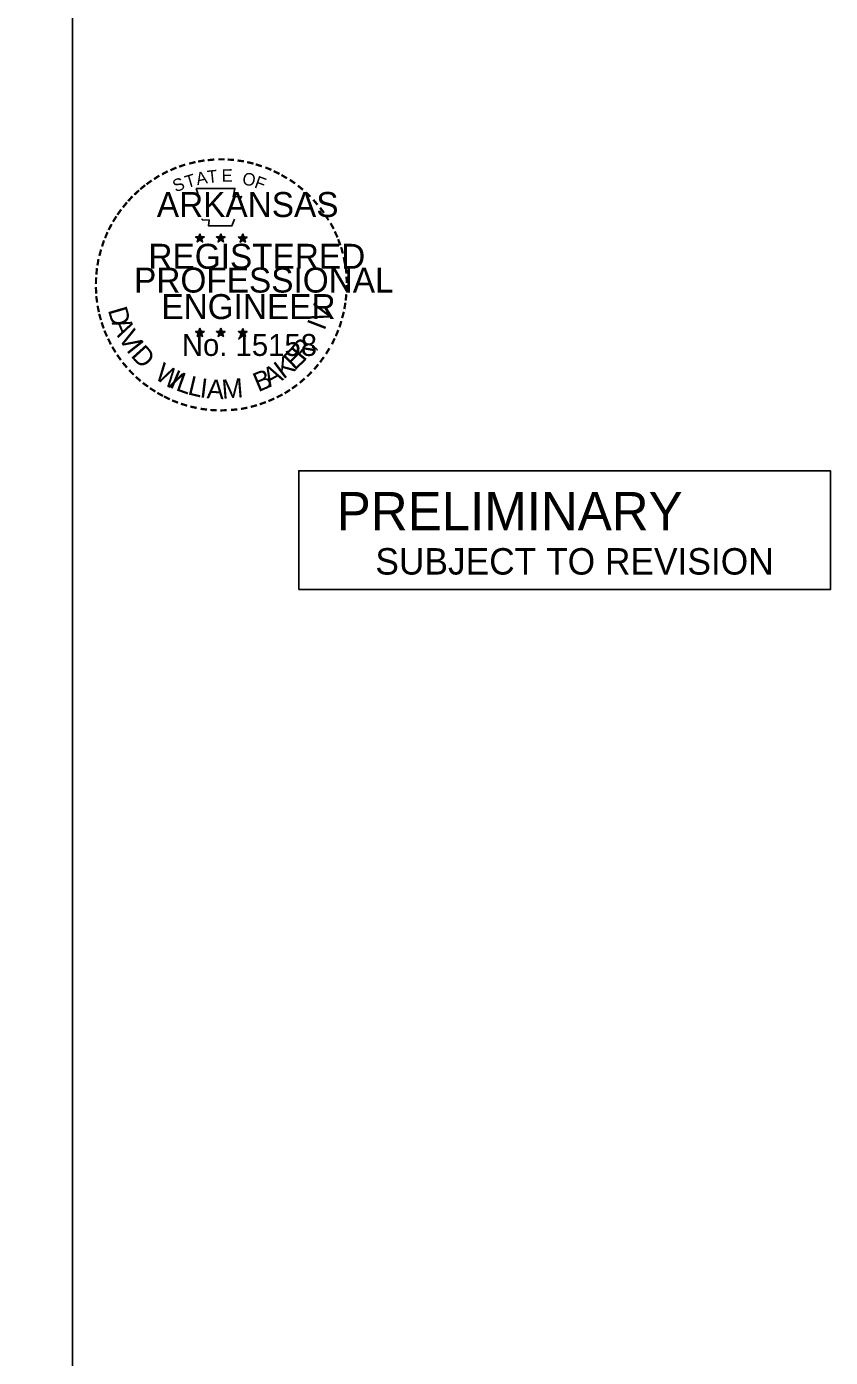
# Model space of a CAD drawing. Extents: x 1371343 to 1376243, y 378740 to 382184.
# Drawn here: x 1373024 to 1373353, y 380374 to 380917 of the extents above; entities that cross this region are included whole.
import ezdxf

# ---------------------------------------------------------------- set-up
doc = ezdxf.new("R2010")
doc.units = 0
for name, color, linetype in [('Default', 7, 'Continuous'), ('R_Border PE', 7, 'Continuous'), ('SHET_Border-Lines', 7, 'Continuous'), ('SHET_Stamp-PE-Chief-Eng', 7, 'Continuous')]:
    doc.layers.add(name, color=color, linetype=linetype)

msp = doc.modelspace()

# ---------------------------------------------------------------- linework, layer by layer
at = {"layer": 'Default'}
for points in [[(1371342.92, 380940.49), (1371342.92, 379840.49), (1373042.92, 379840.49), (1373042.92, 380940.49)], [(1373135.48, 380687.25), (1373352.88, 380687.25), (1373352.88, 380735.79), (1373135.48, 380735.79)]]:
    msp.add_lwpolyline(points, close=True, dxfattribs=at)
at = {"layer": 'R_Border PE'}
for p, q in [((1373095.08, 380832.67), (1373094.87, 380831.39)), ((1373095.08, 380830.81), (1373095.08, 380832.67)), ((1373095.08, 380832.67), (1373095.33, 380831.4)), ((1373103.6, 380832.67), (1373103.39, 380831.39)), ((1373103.6, 380830.81), (1373103.6, 380832.67)), ((1373103.6, 380832.67), (1373103.85, 380831.4)), ((1373112.59, 380832.61), (1373112.38, 380831.33)), ((1373112.59, 380830.75), (1373112.59, 380832.61)), ((1373112.59, 380832.61), (1373112.84, 380831.34)), ((1373093.3, 380831.38), (1373095.08, 380830.81)), ((1373093.3, 380831.38), (1373094.59, 380831.15)), ((1373093.3, 380831.38), (1373094.51, 380830.75)), ((1373093.98, 380829.3), (1373095.08, 380830.81)), ((1373093.98, 380829.3), (1373094.62, 380830.54)), ((1373093.98, 380829.3), (1373095.07, 380830.4)), ((1373096.17, 380829.3), (1373095.07, 380830.39)), ((1373096.85, 380831.38), (1373095.08, 380830.81)), ((1373096.17, 380829.3), (1373095.08, 380830.81)), ((1373096.85, 380831.38), (1373095.39, 380831.13)), ((1373096.17, 380829.3), (1373095.47, 380830.78)), ((1373096.85, 380831.38), (1373095.81, 380830.86)), ((1373101.82, 380831.38), (1373103.6, 380830.81)), ((1373101.82, 380831.38), (1373103.11, 380831.15)), ((1373101.82, 380831.38), (1373103.03, 380830.75)), ((1373102.5, 380829.3), (1373103.6, 380830.81)), ((1373102.5, 380829.3), (1373103.14, 380830.54)), ((1373102.5, 380829.3), (1373103.59, 380830.4)), ((1373104.68, 380829.3), (1373103.59, 380830.39)), ((1373105.37, 380831.38), (1373103.6, 380830.81)), ((1373104.68, 380829.3), (1373103.6, 380830.81)), ((1373105.37, 380831.38), (1373103.91, 380831.13)), ((1373104.68, 380829.3), (1373103.98, 380830.78)), ((1373105.37, 380831.38), (1373104.33, 380830.86)), ((1373110.81, 380831.32), (1373112.59, 380830.75)), ((1373110.81, 380831.32), (1373112.1, 380831.09)), ((1373110.81, 380831.32), (1373112.02, 380830.69)), ((1373111.49, 380829.23), (1373112.59, 380830.75)), ((1373111.49, 380829.23), (1373112.13, 380830.48)), ((1373111.49, 380829.23), (1373112.58, 380830.34)), ((1373113.68, 380829.23), (1373112.58, 380830.33)), ((1373114.36, 380831.32), (1373112.59, 380830.75)), ((1373113.68, 380829.23), (1373112.59, 380830.75)), ((1373114.36, 380831.32), (1373112.9, 380831.07)), ((1373113.68, 380829.23), (1373112.98, 380830.72)), ((1373114.36, 380831.32), (1373113.32, 380830.8)), ((1373095.06, 380794.05), (1373094.85, 380792.77)), ((1373095.06, 380792.19), (1373095.06, 380794.05)), ((1373095.06, 380794.05), (1373095.31, 380792.78)), ((1373103.57, 380794.05), (1373103.36, 380792.77)), ((1373103.57, 380792.19), (1373103.57, 380794.05)), ((1373103.57, 380794.05), (1373103.82, 380792.78)), ((1373112.58, 380794), (1373112.37, 380792.71)), ((1373112.58, 380792.14), (1373112.58, 380794)), ((1373112.58, 380794), (1373112.83, 380792.72)), ((1373093.28, 380792.76), (1373095.06, 380792.19)), ((1373093.28, 380792.76), (1373094.57, 380792.53)), ((1373093.28, 380792.76), (1373094.49, 380792.13)), ((1373093.96, 380790.67), (1373095.06, 380792.19)), ((1373093.96, 380790.67), (1373094.6, 380791.92)), ((1373093.96, 380790.67), (1373095.05, 380791.78)), ((1373096.15, 380790.67), (1373095.05, 380791.77)), ((1373096.83, 380792.76), (1373095.06, 380792.19)), ((1373096.15, 380790.67), (1373095.06, 380792.19)), ((1373096.83, 380792.76), (1373095.37, 380792.51)), ((1373096.15, 380790.67), (1373095.45, 380792.16)), ((1373096.83, 380792.76), (1373095.79, 380792.23)), ((1373101.79, 380792.76), (1373103.57, 380792.19)), ((1373101.79, 380792.76), (1373103.08, 380792.53)), ((1373101.79, 380792.76), (1373103, 380792.13)), ((1373102.47, 380790.67), (1373103.57, 380792.19)), ((1373102.47, 380790.67), (1373103.11, 380791.92)), ((1373102.47, 380790.67), (1373103.56, 380791.78)), ((1373104.66, 380790.67), (1373103.56, 380791.77)), ((1373105.34, 380792.76), (1373103.57, 380792.19)), ((1373104.66, 380790.67), (1373103.57, 380792.19)), ((1373105.34, 380792.76), (1373103.88, 380792.51)), ((1373104.66, 380790.67), (1373103.96, 380792.16)), ((1373105.34, 380792.76), (1373104.3, 380792.23)), ((1373110.8, 380792.7), (1373112.58, 380792.14)), ((1373110.8, 380792.7), (1373112.09, 380792.47)), ((1373110.8, 380792.7), (1373112.01, 380792.08)), ((1373111.48, 380790.62), (1373112.58, 380792.14)), ((1373111.48, 380790.62), (1373112.12, 380791.87)), ((1373111.48, 380790.62), (1373112.57, 380791.73)), ((1373113.67, 380790.62), (1373112.57, 380791.71)), ((1373114.35, 380792.7), (1373112.58, 380792.14)), ((1373113.67, 380790.62), (1373112.58, 380792.14)), ((1373114.35, 380792.7), (1373112.89, 380792.45)), ((1373113.67, 380790.62), (1373112.97, 380792.11)), ((1373114.35, 380792.7), (1373113.31, 380792.18))]:
    msp.add_line(p, q, dxfattribs=at)
for points in [[(1373093.51, 380851.15), (1373094.88, 380846.94)], [(1373111.42, 380846.45), (1373112.14, 380847.9), (1373108.65, 380847.78), (1373109.4, 380851.15), (1373093.51, 380851.15)], [(1373096.02, 380838.8), (1373096.02, 380838.35), (1373098.89, 380838.26), (1373098.61, 380835.84), (1373108.15, 380835.84), (1373109.18, 380838.58)], [(1373103.6, 380832.67), (1373104.68, 380829.3), (1373101.82, 380831.38), (1373105.37, 380831.38), (1373102.5, 380829.3), (1373103.6, 380832.67)], [(1373112.59, 380832.61), (1373113.68, 380829.23), (1373110.81, 380831.32), (1373114.36, 380831.32), (1373111.49, 380829.23), (1373112.59, 380832.61)], [(1373095.06, 380794.05), (1373096.15, 380790.67), (1373093.28, 380792.76), (1373096.83, 380792.76), (1373093.96, 380790.67), (1373095.06, 380794.05)], [(1373103.57, 380794.05), (1373104.66, 380790.67), (1373101.79, 380792.76), (1373105.34, 380792.76), (1373102.47, 380790.67), (1373103.57, 380794.05)], [(1373112.58, 380794), (1373113.67, 380790.62), (1373110.8, 380792.7), (1373114.35, 380792.7), (1373111.48, 380790.62), (1373112.58, 380794)]]:
    msp.add_lwpolyline(points, dxfattribs=at)
for centre, radius in [((1373095.08, 380830.81), 0.878), ((1373103.59, 380830.81), 0.878), ((1373095.08, 380830.81), 0.737), ((1373095.08, 380830.81), 0.59), ((1373095.08, 380830.81), 0.505), ((1373095.08, 380830.81), 0.381), ((1373095.08, 380830.81), 0.253), ((1373095.08, 380830.81), 0.151), ((1373103.59, 380830.81), 0.737), ((1373103.59, 380830.81), 0.59), ((1373103.59, 380830.81), 0.505), ((1373103.59, 380830.81), 0.381), ((1373103.59, 380830.81), 0.253), ((1373103.59, 380830.81), 0.151), ((1373112.59, 380830.74), 0.878), ((1373112.59, 380830.74), 0.737), ((1373112.59, 380830.74), 0.59), ((1373112.59, 380830.74), 0.505), ((1373112.59, 380830.74), 0.381), ((1373112.59, 380830.74), 0.253), ((1373112.59, 380830.74), 0.151), ((1373095.05, 380792.18), 0.878), ((1373095.05, 380792.18), 0.737), ((1373095.05, 380792.18), 0.59), ((1373095.05, 380792.18), 0.505), ((1373095.05, 380792.18), 0.381), ((1373095.05, 380792.18), 0.253), ((1373095.05, 380792.18), 0.151), ((1373103.57, 380792.18), 0.878), ((1373103.57, 380792.18), 0.737), ((1373103.57, 380792.18), 0.59), ((1373103.57, 380792.18), 0.505), ((1373103.57, 380792.18), 0.381), ((1373103.57, 380792.18), 0.253), ((1373103.57, 380792.18), 0.151), ((1373112.58, 380792.13), 0.878), ((1373112.58, 380792.13), 0.737), ((1373112.58, 380792.13), 0.59), ((1373112.58, 380792.13), 0.505), ((1373112.58, 380792.13), 0.381), ((1373112.58, 380792.13), 0.253), ((1373112.58, 380792.13), 0.151)]:
    msp.add_circle(centre, radius, dxfattribs=at)
at = {"layer": 'SHET_Border-Lines'}
msp.add_lwpolyline([(1371342.92, 379840.49), (1373042.92, 379840.49), (1373042.92, 380940.49), (1371342.92, 380940.49)], close=True, dxfattribs=at)
at = {"layer": 'SHET_Stamp-PE-Chief-Eng'}
msp.add_lwpolyline([(1373095.08, 380832.67), (1373096.17, 380829.3), (1373093.3, 380831.38), (1373096.85, 380831.38), (1373093.98, 380829.3), (1373095.08, 380832.67)], dxfattribs=at)

# ---------------------------------------------------------------- texts
at = {"layer": 'Default'}
for s, height, p in [('PRELIMINARY', 15.6, (1373151.04, 380711.52)), ('SUBJECT TO REVISION', 10.8, (1373166.81, 380693.39))]:
    msp.add_text(s, height=height, dxfattribs=at).set_placement(p)
at = {"layer": 'R_Border PE'}
for s, height, rotation, p in [('-', 8.16, 24.3072, (1373083.89, 380855.53)), ('-', 8.16, 19.1761, (1373087.12, 380856.9)), ('-', 8.16, 13.6302, (1373090.95, 380858.13)), ('-', 8.16, 10.2193, (1373094.41, 380858.96)), ('T', 5.1, 6.0228, (1373098.32, 380853.33)), ('-', 8.16, 5.8968, (1373098.12, 380859.52)), ('-', 8.16, 0.1862, (1373102.06, 380859.89)), ('E', 5.1, 0.8323, (1373103.96, 380853.89)), ('-', 8.16, 357.743, (1373105.75, 380859.82)), ('-', 8.16, 352.1617, (1373109.54, 380859.53)), ('-', 8.16, 347.2049, (1373113.21, 380858.95)), ('-', 8.16, 342.3362, (1373116.45, 380858.16)), ('-', 8.16, 337.8551, (1373120.2, 380857.02)), ('-', 8.16, 36.2317, (1373074.67, 380850.01)), ('-', 8.16, 34.0636, (1373077.62, 380852.03)), ('-', 8.16, 28.7918, (1373080.66, 380853.91)), ('S', 5.1, 21.594, (1373085.12, 380849.51)), ('T', 5.1, 16.4036, (1373089.78, 380851.2)), ('A', 5.1, 11.2132, (1373093.99, 380852.48)), ('O', 5.1, 350.4515, (1373112.14, 380852.82)), ('F', 5.1, 340.0707, (1373117, 380851.65)), ('-', 8.16, 334.1211, (1373123.41, 380855.64)), ('-', 8.16, 329.6409, (1373126.37, 380854.2)), ('-', 8.16, 325.8627, (1373129.65, 380852.36)), ('-', 8.16, 48.4231, (1373067.75, 380843.52)), ('-', 8.16, 42.9622, (1373070.03, 380845.96)), ('-', 8.16, 38.9507, (1373072.24, 380848.08)), ('-', 8.16, 320.5297, (1373132.76, 380850.19)), ('-', 8.16, 315.5786, (1373135.81, 380847.7)), ('-', 8.16, 54.2325, (1373063.59, 380838.15)), ('-', 8.16, 50.6142, (1373065.69, 380841.04)), ('-', 8.16, 309.8797, (1373138.71, 380844.89)), ('-', 8.16, 306.6522, (1373141.39, 380841.82)), ('-', 8.16, 58.0706, (1373061.93, 380835.46)), ('-', 7.14, 303.6753, (1373143.87, 380838.92)), ('-', 8.16, 299.6684, (1373145.5, 380835.83)), ('-', 8.16, 67.7743, (1373059.01, 380829.21)), ('-', 8.16, 62.8713, (1373060.33, 380832.33)), ('-', 8.16, 294.6628, (1373147.15, 380832.71)), ('-', 8.16, 75.461, (1373056.89, 380822.36)), ('-', 8.16, 72.3945, (1373057.9, 380826)), ('-', 8.16, 290.5728, (1373148.46, 380829.77)), ('-', 8.16, 285.1233, (1373149.65, 380826.81)), ('-', 8.16, 81.2013, (1373056.22, 380818.72)), ('-', 8.16, 280.5493, (1373150.67, 380823.02)), ('-', 8.16, 85.1863, (1373055.83, 380815.2)), ('-', 8.16, 276.5962, (1373151.5, 380819.11)), ('-', 8.16, 94.1959, (1373055.88, 380807.93)), ('-', 8.16, 89.0622, (1373055.7, 380811.62)), ('-', 8.16, 274.3301, (1373151.81, 380815.42)), ('-', 8.16, 269.9407, (1373151.98, 380812.2)), ('-', 8.16, 98.9479, (1373056.25, 380804.53)), ('V', 7.85, 72.6573, (1373147.11, 380795.57)), ('-', 8.16, 260.9953, (1373151.52, 380805.47)), ('-', 8.16, 263.5172, (1373151.88, 380808.8)), ('-', 8.16, 101.7149, (1373056.94, 380800.79)), ('-', 8.16, 105.4578, (1373057.76, 380797.75)), ('D', 7.85, 286.2848, (1373057.39, 380801.49)), ('-', 8.16, 255.7626, (1373150.96, 380802.01)), ('-', 8.16, 109.0874, (1373058.86, 380794.53)), ('A', 7.85, 292.7835, (1373058.88, 380796.38)), ('V', 7.85, 300.7936, (1373061.5, 380790.37)), ('I', 7.85, 69.0301, (1373145.98, 380792.82)), ('-', 8.16, 252.8681, (1373150.04, 380798.34)), ('-', 8.16, 114.0643, (1373060.16, 380791.5)), ('-', 8.16, 115.7289, (1373061.71, 380788.34)), ('I', 7.85, 308.3502, (1373064.72, 380785.08)), ('R', 7.85, 50.3651, (1373137.56, 380780.13)), ('-', 8.16, 244.6197, (1373147.56, 380791.7)), ('-', 8.16, 247.8887, (1373148.9, 380794.91)), ('-', 8.16, 120.4471, (1373063.53, 380785.36)), ('-', 8.16, 125.8934, (1373065.59, 380782.49)), ('D', 7.85, 311.9774, (1373066.51, 380782.7)), ('K', 7.85, 36.9143, (1373129.18, 380773)), ('E', 7.85, 44.0175, (1373133.81, 380776.52)), (',', 7.85, 57.4684, (1373141.25, 380784.63)), ('-', 8.16, 239.0712, (1373145.55, 380787.86)), ('-', 8.16, 130.7181, (1373067.94, 380779.68)), ('-', 8.16, 134.2238, (1373070.58, 380776.9)), ('W', 7.85, 328.0731, (1373076.09, 380773.7)), ('B', 7.85, 22.8589, (1373118.91, 380767.85)), ('A', 7.85, 28.9042, (1373123.48, 380769.75)), ('-', 8.16, 231.2538, (1373141.31, 380781.65)), ('-', 8.16, 233.8452, (1373143.5, 380784.53)), ('-', 8.16, 138.9338, (1373073.26, 380774.53)), ('-', 8.16, 144.6463, (1373076.09, 380772.46)), ('I', 7.85, 336.6877, (1373082.15, 380770.08)), ('L', 7.85, 340.3149, (1373084.84, 380768.84)), ('L', 7.85, 346.6625, (1373089.74, 380767.08)), ('I', 7.85, 353.0101, (1373094.8, 380765.87)), ('A', 7.85, 356.6373, (1373097.74, 380765.44)), ('M', 7.85, 4.6473, (1373104.29, 380765.14)), ('-', 8.16, 221.0851, (1373136.2, 380776.18)), ('-', 8.16, 225.7653, (1373138.87, 380778.77)), ('-', 8.16, 148.0898, (1373078.95, 380770.57)), ('-', 8.16, 151.5704, (1373081.91, 380768.91)), ('-', 8.16, 154.6002, (1373084.57, 380767.65)), ('-', 8.16, 207.3568, (1373127.84, 380770.03)), ('-', 8.16, 212.2491, (1373130.68, 380771.79)), ('-', 8.16, 215.7363, (1373133.4, 380773.77)), ('-', 8.16, 158.5612, (1373087.75, 380766.36)), ('-', 8.16, 162.7983, (1373091.25, 380765.27)), ('-', 8.16, 167.5555, (1373094.9, 380764.44)), ('-', 8.16, 173.1155, (1373098.84, 380763.87)), ('-', 8.16, 176.5183, (1373102.65, 380763.6)), ('-', 8.16, 181.5918, (1373106.45, 380763.7)), ('-', 8.16, 185.8167, (1373110.57, 380764.09)), ('-', 8.16, 191.2858, (1373114.33, 380764.76)), ('-', 8.16, 195.4743, (1373118.04, 380765.78)), ('-', 8.16, 199.4643, (1373121.43, 380766.99)), ('-', 8.16, 204.2516, (1373124.65, 380768.4))]:
    msp.add_text(s, height=height, rotation=rotation, dxfattribs=at).set_placement(p)
for s, height, p in [('ARKANSAS', 10.2, (1373077.46, 380839.49)), ('REGISTERED', 10.2, (1373074, 380818.33)), ('PROFESSIONAL', 10.1998, (1373068.15, 380808.62)), ('ENGINEER', 10.2, (1373079.3, 380797.78)), ('No. 15158', 8.961, (1373087.67, 380782.73)), ('AAMU', 0.000102, (1373103.23, 380765.11))]:
    msp.add_text(s, height=height, dxfattribs=at).set_placement(p)

doc.saveas('drawing.dxf')
